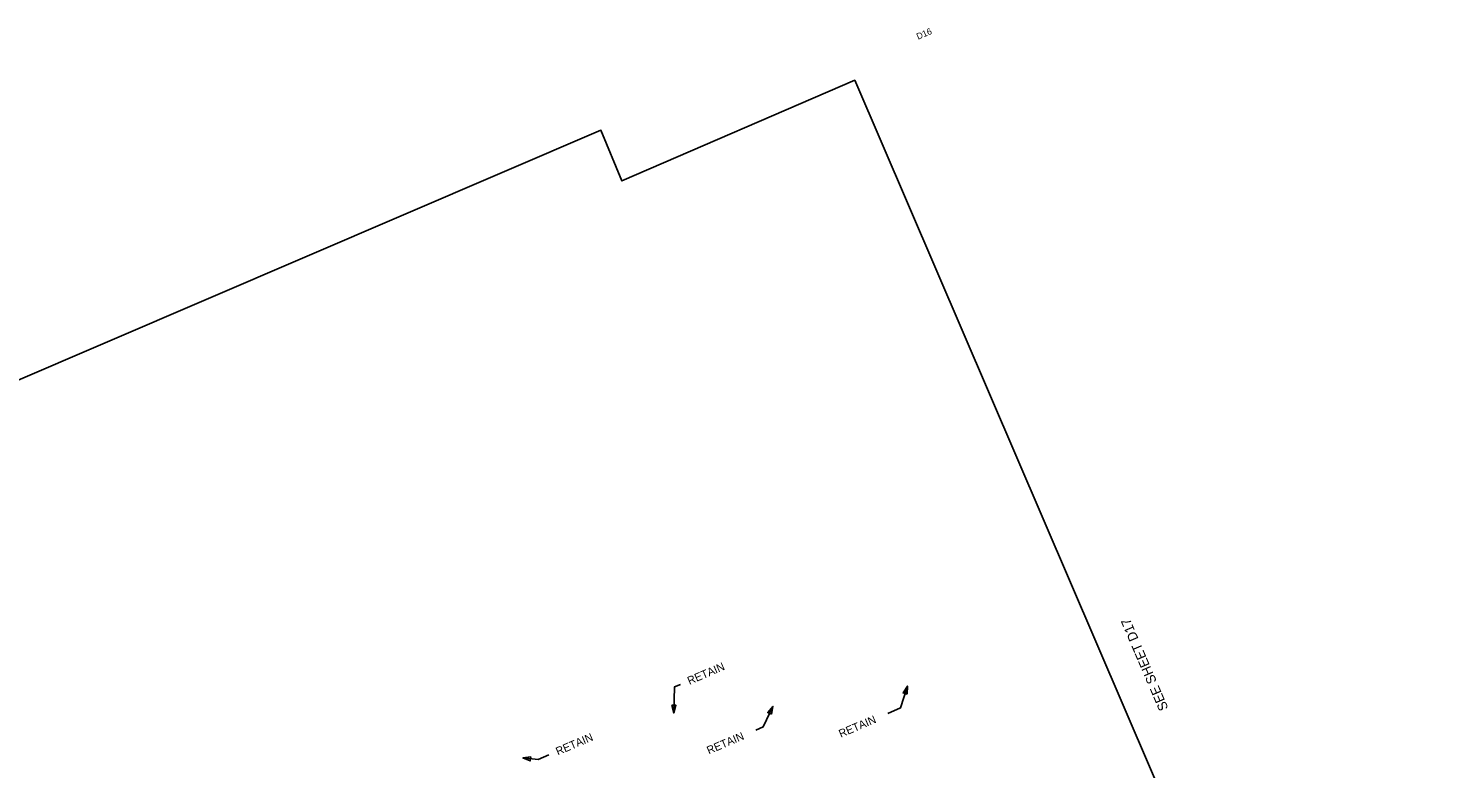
# Model space of a CAD drawing. Extents: x 1619705 to 1621490, y 1101723 to 1103701.
# Drawn here: x 1620580 to 1621456, y 1102790 to 1103253 of the extents above; entities that cross this region are included whole.
import ezdxf

# ---------------------------------------------------------------- set-up
doc = ezdxf.new("R2010")
doc.units = 0
for name, color, linetype in [('Level 2', 7, 'Continuous'), ('Level 8', 7, 'Continuous'), ('RD_HC_Data_Tic', 7, 'Continuous'), ('RFP', 7, 'Continuous')]:
    doc.layers.add(name, color=color, linetype=linetype)

msp = doc.modelspace()

# ---------------------------------------------------------------- linework, layer by layer
at = {"layer": 'Level 2'}
for points in [[(1620988.15, 1102842.33), (1620984.36, 1102840.7), (1620983.87, 1102824.48)], [(1621117.6, 1102824.2), (1621125.59, 1102827.62), (1621129.9, 1102841.26)], [(1621035.13, 1102813.78), (1621039.82, 1102815.79), (1621045.91, 1102828.54)], [(1620905.93, 1102798.19), (1620899.19, 1102795.29), (1620889.65, 1102796.32)]]:
    msp.add_lwpolyline(points, dxfattribs=at)
for points in [[(1621129.68, 1102836.26), (1621129.9, 1102841.26), (1621127.21, 1102837.04)], [(1620982.72, 1102829.34), (1620983.87, 1102824.48), (1620985.31, 1102829.27)], [(1621045, 1102823.63), (1621045.91, 1102828.54), (1621042.66, 1102824.74)], [(1620894.59, 1102797.09), (1620889.65, 1102796.32), (1620894.31, 1102794.52)]]:
    msp.add_lwpolyline(points, close=True, dxfattribs=at)
at = {"layer": 'RFP'}
msp.add_lwpolyline([(1620077.33, 1101792.57), (1621455.74, 1102384.16), (1621344.3, 1102622.52), (1621323.62, 1102755.47), (1621298.88, 1102749.66), (1621097.02, 1103220), (1620951.48, 1103157.13), (1620938.43, 1103188.78), (1619705.25, 1102659.52)], close=True, dxfattribs=at)
msp.add_lwpolyline([(1620077.33, 1101792.57), (1621455.74, 1102384.16), (1621344.3, 1102622.52), (1621323.62, 1102755.47), (1621298.88, 1102749.66), (1621097.02, 1103220), (1620951.48, 1103157.13), (1620938.43, 1103188.78), (1619705.25, 1102659.52)], close=True, dxfattribs=at)
msp.add_lwpolyline([(1620077.33, 1101792.57), (1621455.74, 1102384.16), (1621344.3, 1102622.52), (1621323.62, 1102755.47), (1621298.88, 1102749.66), (1621097.02, 1103220), (1620951.48, 1103157.13), (1620938.43, 1103188.78), (1619705.25, 1102659.52)], close=True, dxfattribs=at)
msp.add_lwpolyline([(1620077.33, 1101792.57), (1621455.74, 1102384.16), (1621344.3, 1102622.52), (1621323.62, 1102755.47), (1621298.88, 1102749.66), (1621097.02, 1103220), (1620951.48, 1103157.13), (1620938.43, 1103188.78), (1619705.25, 1102659.52)], close=True, dxfattribs=at)
msp.add_lwpolyline([(1620077.33, 1101792.57), (1621455.74, 1102384.16), (1621344.3, 1102622.52), (1621323.62, 1102755.47), (1621298.88, 1102749.66), (1621097.02, 1103220), (1620951.48, 1103157.13), (1620938.43, 1103188.78), (1619705.25, 1102659.52)], close=True, dxfattribs=at)

# ---------------------------------------------------------------- texts
at = {"layer": 'Level 2'}
for p in [(1620993.73, 1102842), (1621088.31, 1102808.9), (1620911.51, 1102797.86), (1621005.84, 1102798.49)]:
    msp.add_text('RETAIN', height=5, rotation=23.22835, dxfattribs=at).set_placement(p)
at = {"layer": 'Level 8'}
msp.add_text('D16', height=4, rotation=23.22835, dxfattribs=at).set_placement((1621136.59, 1103245.33))
at = {"layer": 'RD_HC_Data_Tic'}
msp.add_text('SEE SHEET D17', height=6, rotation=113.22835, dxfattribs=at).set_placement((1621293.03, 1102827.37))

doc.saveas('drawing.dxf')
